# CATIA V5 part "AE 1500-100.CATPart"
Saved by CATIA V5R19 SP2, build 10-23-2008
Part number: AE 1500-100
Bounding box of the stored display mesh (mm): x -37.351 to 37.351, y -37.351 to 37.351, z 0 to 260
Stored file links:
  C:\Users\Bora\Desktop\3D Katı model\AE serisi\AE 1500\AE 1500-100.CATPart
  C:\Program Files\Dassault Systemes\B19\intel_a\reffiles\standard\MetricThickPitch.txt
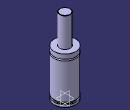
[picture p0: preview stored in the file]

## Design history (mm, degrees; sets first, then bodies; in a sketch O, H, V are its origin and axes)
Body1 (main body)
  Sketch1 on yz-plane, origin (0, 0, 0), H (0, 1, 0), V (0, 0, 1)
    point P1 (37.5, 143.5)
    point P5 (18, 259)
    point P7 (18, 259)
    point P12 (37.5, 138.5)
    point P13 (37.5, 143.5)
    point P14 (37.5, 138.5)
    line L1 (37.5, 143.5) -> (37.5, 159)
    line L2 (37.5, 0) -> (37.5, 8)
    arc A1 centre (17, 259) radius 1 from (18, 259) to (17, 260) ccw
    line L3 (18, 259) -> (18, 159)
    line L4 (33.5, 15) -> (33.5, 8)
    line L5 (37.5, 15) -> (37.5, 138.5)
    arc A2 centre (37.5, 141) radius 2.5 from (37.5, 143.5) to (37.5, 138.5) ccw
    line L6 (17, 260) -> (0, 260)
    point P15 (0, 260)
    line L7 (18, 159) -> (37.5, 159)
    line L8 (0, 0) -> (37.5, 0)
    line L9 (33.5, 15) -> (37.5, 15)
    line L10 (33.5, 8) -> (37.5, 8)
    coincidence: P15 V, P1 P13, P5 P7, P12 P14
    tangency: L6 A1
    horizontal: L7 H, L8 H, L9 H, L10 H
  Shaft1: profile Sketch1, axis Sketch1.V, angle 360
  Sketch2 on face of Shaft1 from Sketch1.L8, origin (0, 0, 0), H (1, 0, 0), V (0, -1, 0)
    point P1 (20, 0)
    distance P1 V = 20
  Hole1: placed by Sketch2, at (20, 0, 0) direction (0, 0, 1), diameter 6.647, depth 13, threaded "M8", thread diameter 8, thread depth 13, pitch 1.25
  CircPattern1: of Hole1, instances 4, angular step 90, axis from xy-plane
